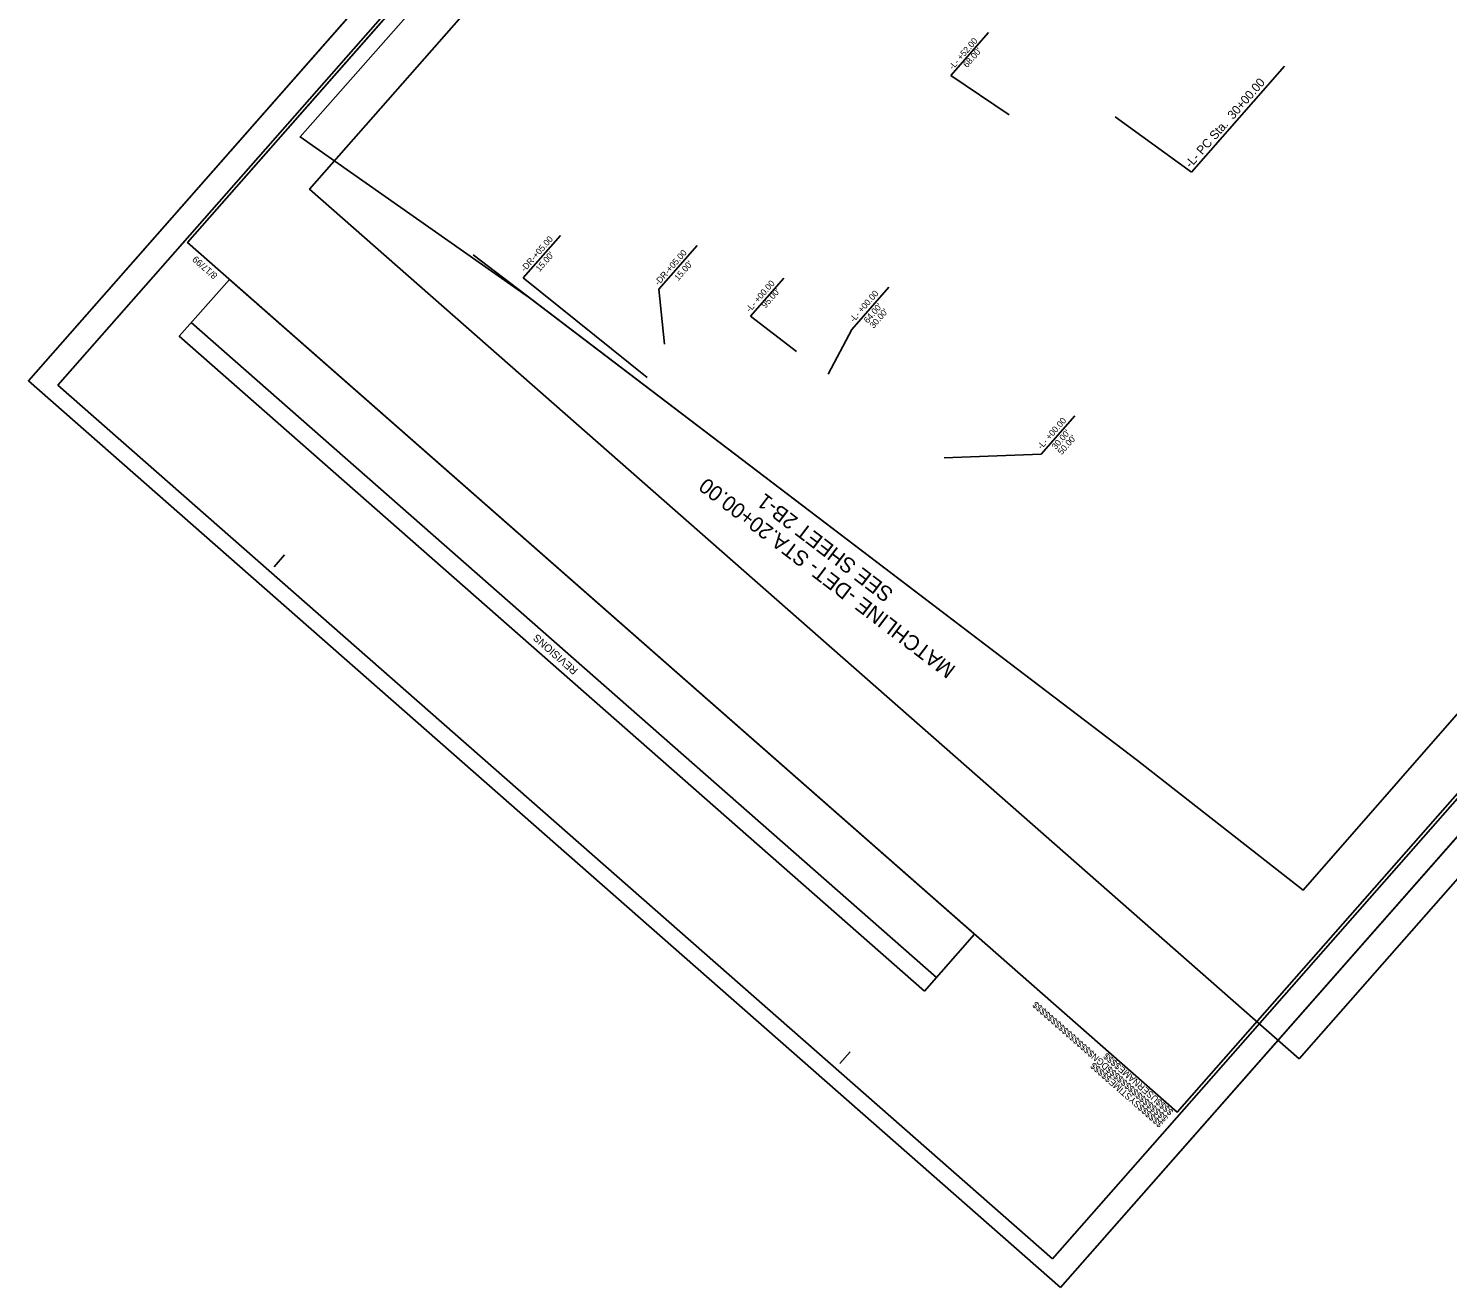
# Model space of a CAD drawing. Extents: x 2189835 to 2191772, y 387461 to 389531.
# Drawn here: x 2189835 to 2190965, y 387461 to 388465 of the extents above; entities that cross this region are included whole.
import ezdxf

# ---------------------------------------------------------------- set-up
doc = ezdxf.new("R2010")
doc.units = 0
for name, color, linetype in [('Matchline', 7, 'Continuous'), ('Matchline Text', 7, 'Continuous'), ('Prop DSN Text', 7, 'Continuous'), ('Prop Easement Construction Station Offsets', 7, 'Continuous'), ('Prop Horizontal Alignment Station Label', 7, 'Continuous'), ('Sheet Block Revision CELL', 7, 'Continuous'), ('Sheet Clip Boundary CELL', 7, 'Continuous'), ('Sheet Cutting Line CELL', 7, 'Continuous'), ('Sheet Layout Plan Border', 7, 'Continuous'), ('Sheet Plan CELL', 7, 'Continuous'), ('Sheet Plan Layout CELL', 7, 'Continuous'), ('Sheet Plot Border Inside CELL', 7, 'Continuous'), ('Sheet Plot Border Outside CELL', 7, 'Continuous')]:
    doc.layers.add(name, color=color, linetype=linetype)

msp = doc.modelspace()

# ---------------------------------------------------------------- linework, layer by layer
at = {"layer": 'Matchline'}
msp.add_line((2190188.9, 388284.5), (2190718.4, 387881.3), dxfattribs=at)
at = {"layer": 'Prop DSN Text'}
for p, q in [((2190569.5, 388427.4), (2190599.5, 388461.6)), ((2190616, 388396.1), (2190569.5, 388427.4)), ((2190228.7, 388266), (2190258.5, 388300)), ((2190336.8, 388257), (2190367.4, 388291.8)), ((2190327.5, 388186.7), (2190228.7, 388266)), ((2190409.9, 388235.6), (2190436.5, 388265.9)), ((2190341.5, 388213.2), (2190336.8, 388257)), ((2190490.6, 388225), (2190520.3, 388258.7)), ((2190446.7, 388207.5), (2190409.9, 388235.6)), ((2190471.8, 388189.4), (2190490.6, 388225)), ((2190641.7, 388125.6), (2190668.5, 388156.2)), ((2190564.3, 388122.7), (2190641.7, 388125.6))]:
    msp.add_line(p, q, dxfattribs=at)
at = {"layer": 'Prop Horizontal Alignment Station Label'}
for p, q in [((2190761.5, 388350.4), (2190835.4, 388435)), ((2190700.5, 388394.4), (2190761.5, 388350.4))]:
    msp.add_line(p, q, dxfattribs=at)
at = {"layer": 'Sheet Block Revision CELL'}
msp.add_line((2190558.1, 387708.4), (2189964.3, 388230.4), dxfattribs=at)
msp.add_lwpolyline([(2190548.5, 387697.4), (2189954.7, 388219.5), (2189994.7, 388264.9), (2190588.5, 387742.9)], close=True, dxfattribs=at)
at = {"layer": 'Sheet Clip Boundary CELL'}
msp.add_lwpolyline([(2190233.9, 388250.3), (2190718.4, 387881.3), (2190850.4, 387778), (2191678.6, 388725.5), (2191058.6, 389246.4), (2190957.7, 389128), (2190818.1, 389247.9), (2190051, 388378.5)], close=True, dxfattribs=at)
at = {"layer": 'Sheet Cutting Line CELL'}
for p, q in [((2190946.1, 389448.4), (2189834.5, 388184)), ((2190656.9, 387461), (2191768.5, 388725.4)), ((2189834.5, 388184), (2190656.9, 387461))]:
    msp.add_line(p, q, dxfattribs=at)
at = {"layer": 'Sheet Layout Plan Border'}
msp.add_lwpolyline([(2190847.2, 387643.5), (2191771.6, 388694.9), (2191141.8, 389248.6), (2191016.9, 389106.4), (2190858, 389246.1), (2190058.6, 388336.8)], close=True, dxfattribs=at)
at = {"layer": 'Sheet Plan CELL'}
for p, q in [((2189961.4, 388294.2), (2189961.4, 388294.2)), ((2190030.4, 388035.8), (2190038.7, 388045.2)), ((2190481.1, 387639.6), (2190489.3, 387649)), ((2190749.9, 387600.9), (2190749.9, 387600.9))]:
    msp.add_line(p, q, dxfattribs=at)
for points in [[(2190951.8, 389420.8), (2189961.4, 388294.2), (2190749.9, 387600.9), (2191740.3, 388727.5)], [(2190749.9, 387600.9), (2189961.4, 388294.2), (2190819.7, 389270.5), (2190932.4, 389171.5), (2191064.5, 389321.7), (2191740.3, 388727.5)]]:
    msp.add_lwpolyline(points, close=True, dxfattribs=at)
at = {"layer": 'Sheet Plan Layout CELL'}
msp.add_lwpolyline([(2189961.4, 388294.2), (2190749.9, 387600.9), (2191740.3, 388727.5), (2191110.6, 389281.1), (2190952.6, 389101.4), (2190793.8, 389241.1)], close=True, dxfattribs=at)
at = {"layer": 'Sheet Plot Border Inside CELL'}
msp.add_lwpolyline([(2190650.5, 387484), (2191750.5, 388735.2), (2190958.2, 389431.8), (2189858.1, 388180.6)], close=True, dxfattribs=at)
at = {"layer": 'Sheet Plot Border Outside CELL'}
msp.add_lwpolyline([(2190656.9, 387461), (2191768.5, 388725.4), (2190946.1, 389448.4), (2189834.5, 388184)], close=True, dxfattribs=at)

# ---------------------------------------------------------------- texts
at = {"layer": 'Matchline Text'}
for s, p in [('MATCHLINE -DET- STA.20+00.00', (2190574.3, 387955.6)), ('SEE SHEET 2B-1', (2190524.8, 388016.2))]:
    msp.add_text(s, height=12.15, rotation=142.7074, dxfattribs=at).set_placement(p)
at = {"layer": 'Prop DSN Text'}
for s, p in [('-L- +52.00', (2190571.2, 388431.7)), ("68.00'", (2190582.6, 388433.3)), ("68.00'", (2190582.6, 388433.3)), ('-DR-+05.00', (2190230.1, 388270.6)), ("15.00'", (2190241.9, 388270.6)), ('-DR-+05.00', (2190336.7, 388259.7)), ("15.00'", (2190352.4, 388263.4)), ('-L- +00.00', (2190409.5, 388238.4)), ("95.00'", (2190422, 388241.6)), ('-L- +00.00', (2190492.2, 388230.3)), ("64.00'", (2190503.4, 388229.5)), ("30.00'", (2190508.1, 388225.4)), ('-L- +00.00', (2190641.8, 388129)), ("30.00'", (2190653.2, 388128.8)), ("50.00'", (2190658, 388124.6))]:
    msp.add_text(s, height=5, rotation=48.8015, dxfattribs=at).set_placement(p)
at = {"layer": 'Prop Easement Construction Station Offsets'}
for s, p in [('-L- +52.00', (2190571.2, 388431.7)), ("68.00'", (2190582.6, 388433.3))]:
    msp.add_text(s, height=5, rotation=48.8015, dxfattribs=at).set_placement(p)
at = {"layer": 'Prop Horizontal Alignment Station Label'}
msp.add_text('-L- PC Sta.  30+00.00', height=7, rotation=48.8287, dxfattribs=at).set_placement((2190760.7, 388353.2))
at = {"layer": 'Sheet Block Revision CELL'}
msp.add_text('REVISIONS', height=6, rotation=138.6794, dxfattribs=at).set_placement((2190272.9, 387953.7))
at = {"layer": 'Sheet Plan CELL'}
for s, p in [('8/17/99', (2189985.7, 388268.5)), ('$$$$$$$$$$$$$$$$DGN$$$$$$$$$$$$$$$$', (2190743.1, 387596.7)), ('$$$$$$SYSTIME$$$$$', (2190739.1, 387592.2)), ('$$$$USERNAME$$$$', (2190747.4, 387601.7))]:
    msp.add_text(s, height=5.25, rotation=138.6794, dxfattribs=at).set_placement(p)

doc.saveas('drawing.dxf')
